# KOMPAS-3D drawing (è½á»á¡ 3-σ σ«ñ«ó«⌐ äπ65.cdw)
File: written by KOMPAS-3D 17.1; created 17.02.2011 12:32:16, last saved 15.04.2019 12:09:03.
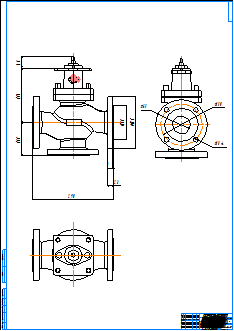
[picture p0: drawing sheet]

Title block, sheet 1: name: Клапан 3-х ходовой Ду65; material: Внимание! Данный продукт является объектом авторского права ООО «Торговый Дом АДЛ». / Запрещается изменение, копирование, распространение / (в том числе путем копирования на другие сайты и ресурсы в Интернете) / или любое иное использование информации и объектов без предварительного / согласия правообладателя (ООО «Торговый Дом АДЛ»).; scale: 1:1; sheets: 1; organisation: ООО "Торговый дом АДЛ"; sheet format: A0; stored path: \\adlc.lan\data\АДЛ_ПКД\3D-модели\ADL production\Клапаны ГРАНРЕГ\Трёхходовой клапан КМ307Ф\KOMPAS 2D\Клапан 3-х ходовой Ду65.cdw

Views: Спереди 1, Проекционный вид 2, Проекционный вид 3
Dimensions and other numbers on the sheet: 120; 196; 43; 290; 3; 23; 185; 150; 18; 65; 1:1; 1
